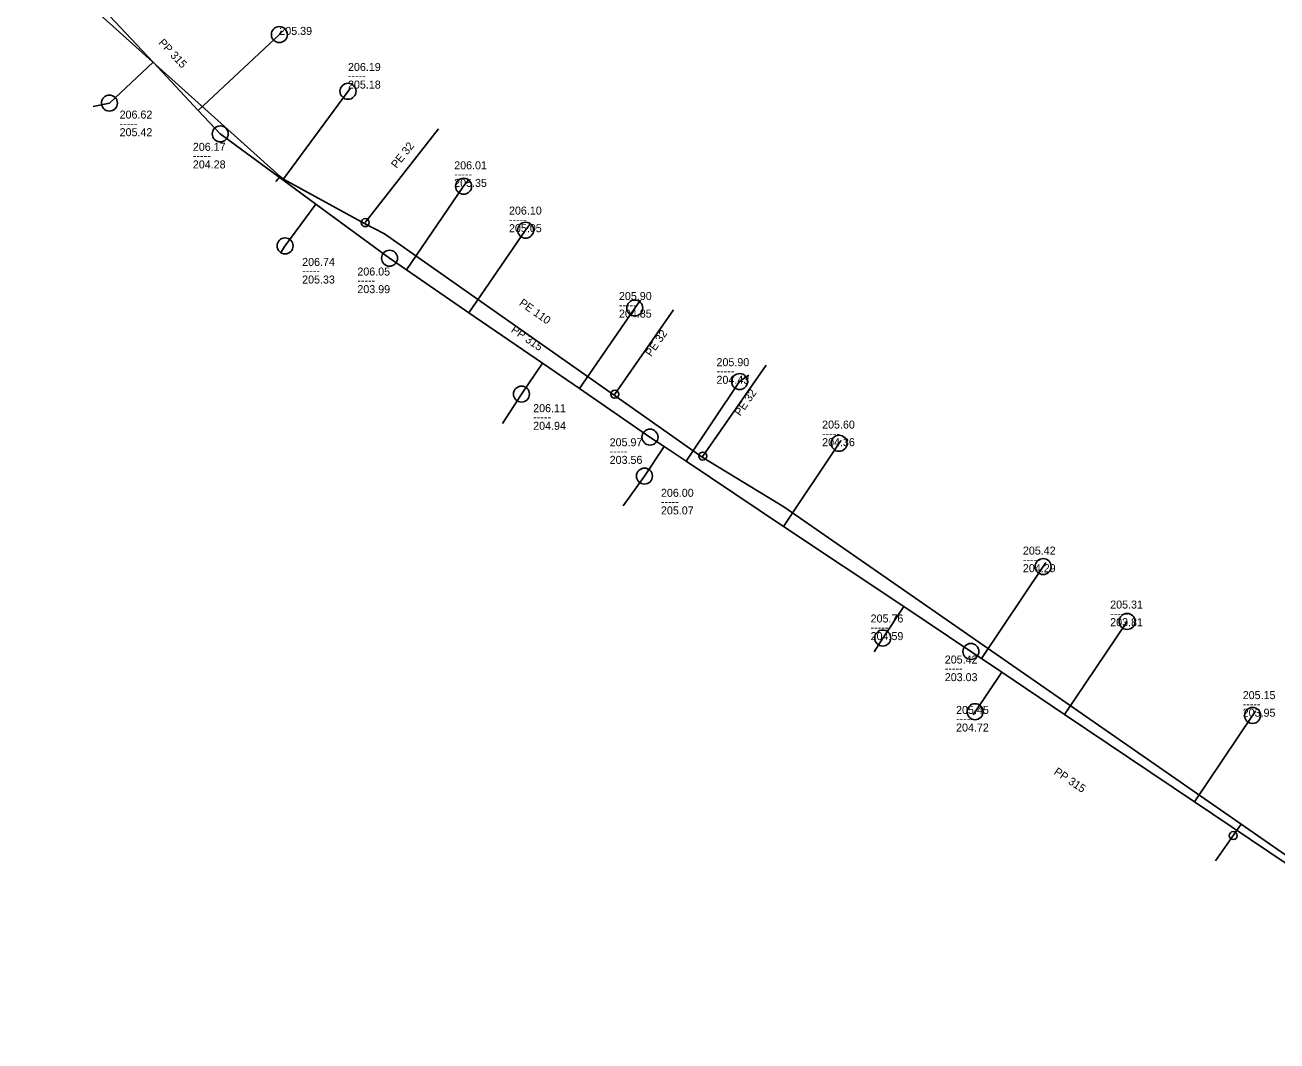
# Model space of a CAD drawing. Extents: x -695225 to -694112, y -1052622 to -1052029.
# Drawn here: x -695106.6 to -694950.1, y -1052358.3 to -1052231.3 of the extents above; entities that cross this region are included whole.
import ezdxf

# ---------------------------------------------------------------- set-up
doc = ezdxf.new("R2010")
doc.units = 0
doc.layers.add('Level 0', color=7, linetype='Continuous')

msp = doc.modelspace()

# ---------------------------------------------------------------- linework, layer by layer
at = {"layer": 'Level 0'}
for p, q in [((-695106.55, -1052221.56), (-695074.65, -1052250.23)), ((-695098.02, -1052227.95), (-695090.54, -1052235.95)), ((-695074.44, -1052232.05), (-695074.77, -1052232.5)), ((-695074.77, -1052232.5), (-695084.9, -1052241.98)), ((-695096.01, -1052241.06), (-695090.54, -1052235.95)), ((-695090.54, -1052235.95), (-695084.9, -1052241.98)), ((-695066.19, -1052239.59), (-695074.32, -1052250.66)), ((-695065.86, -1052239.18), (-695066.19, -1052239.59)), ((-695098.05, -1052241.47), (-695096.01, -1052241.06)), ((-695084.9, -1052241.98), (-695082.15, -1052244.91)), ((-695064.04, -1052256.01), (-695054.89, -1052244.3)), ((-695082.15, -1052244.91), (-695074.32, -1052250.66)), ((-695075.19, -1052250.85), (-695074.65, -1052250.23)), ((-695074.65, -1052250.23), (-695074.24, -1052250.58)), ((-695074.32, -1052250.66), (-695070.21, -1052253.68)), ((-695074.24, -1052250.58), (-695064.13, -1052256.12)), ((-695051.15, -1052250.7), (-695051.74, -1052251.46)), ((-695051.74, -1052251.46), (-695058.9, -1052261.89)), ((-695074.08, -1052258.96), (-695070.21, -1052253.68)), ((-695070.21, -1052253.68), (-695061, -1052260.45)), ((-695064.13, -1052256.12), (-695061.64, -1052257.41)), ((-695043.99, -1052256.95), (-695051.07, -1052267.27)), ((-695043.48, -1052256.23), (-695043.99, -1052256.95)), ((-695061.64, -1052257.41), (-695032.93, -1052277.58)), ((-695074.6, -1052259.75), (-695074.08, -1052258.96)), ((-695061, -1052260.45), (-695058.9, -1052261.89)), ((-695058.9, -1052261.89), (-695051.07, -1052267.27)), ((-695030.36, -1052266.68), (-695037.27, -1052276.75)), ((-695029.65, -1052265.71), (-695030.36, -1052266.68)), ((-695051.07, -1052267.27), (-695041.87, -1052273.59)), ((-695032.85, -1052277.46), (-695025.5, -1052266.92)), ((-695044.51, -1052277.44), (-695041.87, -1052273.59)), ((-695041.87, -1052273.59), (-695037.27, -1052276.75)), ((-695021.85, -1052285.19), (-695013.94, -1052273.82)), ((-695017.25, -1052275.87), (-695023.91, -1052285.84)), ((-695016.09, -1052275.08), (-695017.25, -1052275.87)), ((-695046.87, -1052281.11), (-695044.51, -1052277.44)), ((-695037.27, -1052276.75), (-695028.45, -1052282.82)), ((-695032.93, -1052277.58), (-695032.85, -1052277.46)), ((-695032.93, -1052277.58), (-695021.93, -1052285.32)), ((-695028.45, -1052282.82), (-695026.68, -1052284)), ((-695004.82, -1052283.59), (-695011.75, -1052293.97)), ((-695004.55, -1052283.26), (-695004.82, -1052283.59)), ((-695029.14, -1052287.69), (-695026.68, -1052284)), ((-695026.68, -1052284), (-695023.91, -1052285.84)), ((-695021.93, -1052285.32), (-695021.85, -1052285.19)), ((-695021.93, -1052285.32), (-695011.74, -1052291.52)), ((-695023.91, -1052285.84), (-695011.75, -1052293.97)), ((-695031.82, -1052291.4), (-695029.14, -1052287.69)), ((-695011.74, -1052291.52), (-694954.58, -1052331.21)), ((-695011.75, -1052293.97), (-694996.74, -1052304)), ((-694979.32, -1052299), (-694987.01, -1052310.5)), ((-694978.99, -1052298.51), (-694979.32, -1052299)), ((-694999.37, -1052307.93), (-694996.74, -1052304)), ((-694996.74, -1052304), (-694988.35, -1052309.61)), ((-694968.83, -1052305.85), (-694976.66, -1052317.48)), ((-695000.45, -1052309.66), (-694999.37, -1052307.93)), ((-694988.35, -1052309.61), (-694987.01, -1052310.51)), ((-694987.01, -1052310.51), (-694984.5, -1052312.2)), ((-694987.83, -1052317.14), (-694984.5, -1052312.2)), ((-694984.5, -1052312.2), (-694976.66, -1052317.48)), ((-694988.08, -1052317.54), (-694987.83, -1052317.14)), ((-694976.66, -1052317.48), (-694960.42, -1052328.4)), ((-694953.15, -1052317.6), (-694960.42, -1052328.4)), ((-694952.8, -1052317.08), (-694953.15, -1052317.6)), ((-694960.42, -1052328.4), (-694943.9, -1052339.52)), ((-694957.77, -1052335.79), (-694954.58, -1052331.21)), ((-694954.58, -1052331.21), (-694915.56, -1052358.3))]:
    msp.add_line(p, q, dxfattribs=at)
for centre, radius in [((-695074.77, -1052232.5), 1), ((-695066.19, -1052239.59), 1), ((-695096.01, -1052241.06), 1), ((-695082.15, -1052244.91), 1), ((-695051.74, -1052251.46), 1), ((-695064.04, -1052256.01), 0.5), ((-695043.99, -1052256.95), 1), ((-695074.05, -1052258.91), 1), ((-695061, -1052260.45), 1), ((-695030.36, -1052266.68), 1), ((-695017.25, -1052275.87), 1), ((-695044.51, -1052277.44), 1), ((-695032.85, -1052277.46), 0.5), ((-695028.45, -1052282.82), 1), ((-695004.82, -1052283.59), 1), ((-695021.85, -1052285.19), 0.5), ((-695029.14, -1052287.69), 1), ((-694979.32, -1052299), 1), ((-694968.83, -1052305.85), 1), ((-694999.37, -1052307.93), 1), ((-694988.35, -1052309.61), 1), ((-694987.83, -1052317.14), 1), ((-694953.15, -1052317.6), 1), ((-694955.57, -1052332.63), 0.5)]:
    msp.add_circle(centre, radius, dxfattribs=at)

# ---------------------------------------------------------------- texts
for s, p in [('205.39', (-695074.77, -1052232.54)), ('206.19', (-695066.19, -1052237.05)), ('-----', (-695066.19, -1052238.15)), ('205.18', (-695066.19, -1052239.25)), ('206.62', (-695094.73, -1052243)), ('-----', (-695094.73, -1052244.1)), ('205.42', (-695094.73, -1052245.2)), ('206.17', (-695085.58, -1052247.03)), ('-----', (-695085.58, -1052248.13)), ('204.28', (-695085.58, -1052249.23)), ('206.01', (-695052.92, -1052249.34)), ('-----', (-695052.92, -1052250.44)), ('205.35', (-695052.92, -1052251.54)), ('206.10', (-695046.07, -1052255)), ('-----', (-695046.07, -1052256.1)), ('205.05', (-695046.07, -1052257.2)), ('206.74', (-695071.92, -1052261.42)), ('-----', (-695071.92, -1052262.52)), ('206.05', (-695065.02, -1052262.62)), ('205.33', (-695071.92, -1052263.62)), ('-----', (-695065.02, -1052263.72)), ('203.99', (-695065.02, -1052264.82)), ('205.90', (-695032.33, -1052265.68)), ('-----', (-695032.33, -1052266.78)), ('204.85', (-695032.33, -1052267.88)), ('205.90', (-695020.14, -1052273.95)), ('-----', (-695020.14, -1052275.05)), ('204.43', (-695020.14, -1052276.15)), ('206.11', (-695043.05, -1052279.7)), ('-----', (-695043.05, -1052280.8)), ('205.60', (-695006.94, -1052281.75)), ('204.94', (-695043.05, -1052281.9)), ('-----', (-695006.94, -1052282.85)), ('205.97', (-695033.49, -1052283.96)), ('204.36', (-695006.94, -1052283.95)), ('-----', (-695033.49, -1052285.06)), ('203.56', (-695033.49, -1052286.16)), ('206.00', (-695027.08, -1052290.28)), ('-----', (-695027.08, -1052291.38)), ('205.07', (-695027.08, -1052292.48)), ('205.42', (-694981.85, -1052297.5)), ('-----', (-694981.85, -1052298.6)), ('204.29', (-694981.85, -1052299.7)), ('205.31', (-694970.94, -1052304.25)), ('205.76', (-695000.88, -1052305.99)), ('-----', (-694970.94, -1052305.35)), ('203.81', (-694970.94, -1052306.45)), ('-----', (-695000.88, -1052307.09)), ('204.59', (-695000.88, -1052308.19)), ('205.42', (-694991.61, -1052311.12)), ('-----', (-694991.61, -1052312.22)), ('203.03', (-694991.61, -1052313.32)), ('205.15', (-694954.38, -1052315.57)), ('205.45', (-694990.2, -1052317.42)), ('-----', (-694954.38, -1052316.67)), ('203.95', (-694954.38, -1052317.77)), ('-----', (-694990.2, -1052318.52)), ('204.72', (-694990.2, -1052319.62))]:
    msp.add_text(s, height=1, dxfattribs=at).set_placement(p)
for s, rotation, p in [('PP 315', 313.076, (-695089.94, -1052233.58)), ('PE 32', 51.997, (-695060.11, -1052249.3)), ('PE 110', 324.868, (-695044.89, -1052266.25)), ('PP 315', 325.513, (-695045.9, -1052269.61)), ('PE 32', 55.11, (-695028.31, -1052272.83)), ('PE 32', 55.174, (-695017.16, -1052280.26)), ('PP 315', 326.041, (-694978.06, -1052324.87))]:
    msp.add_text(s, height=1, rotation=rotation, dxfattribs=at).set_placement(p)

doc.saveas('drawing.dxf')
